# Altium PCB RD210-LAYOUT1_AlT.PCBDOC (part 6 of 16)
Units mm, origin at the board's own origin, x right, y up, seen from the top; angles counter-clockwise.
Board outline 330 x 300 mm, 6 copper layers (TOP, Mid-Layer 1, Mid-Layer 2, Mid-Layer 3, Mid-Layer 4, BOTTOM), stack 1.422 mm thick; 981 components, 463 nets, 2326 pads, 12534 vias.
Unrouted connection lines stored in the file: 6.
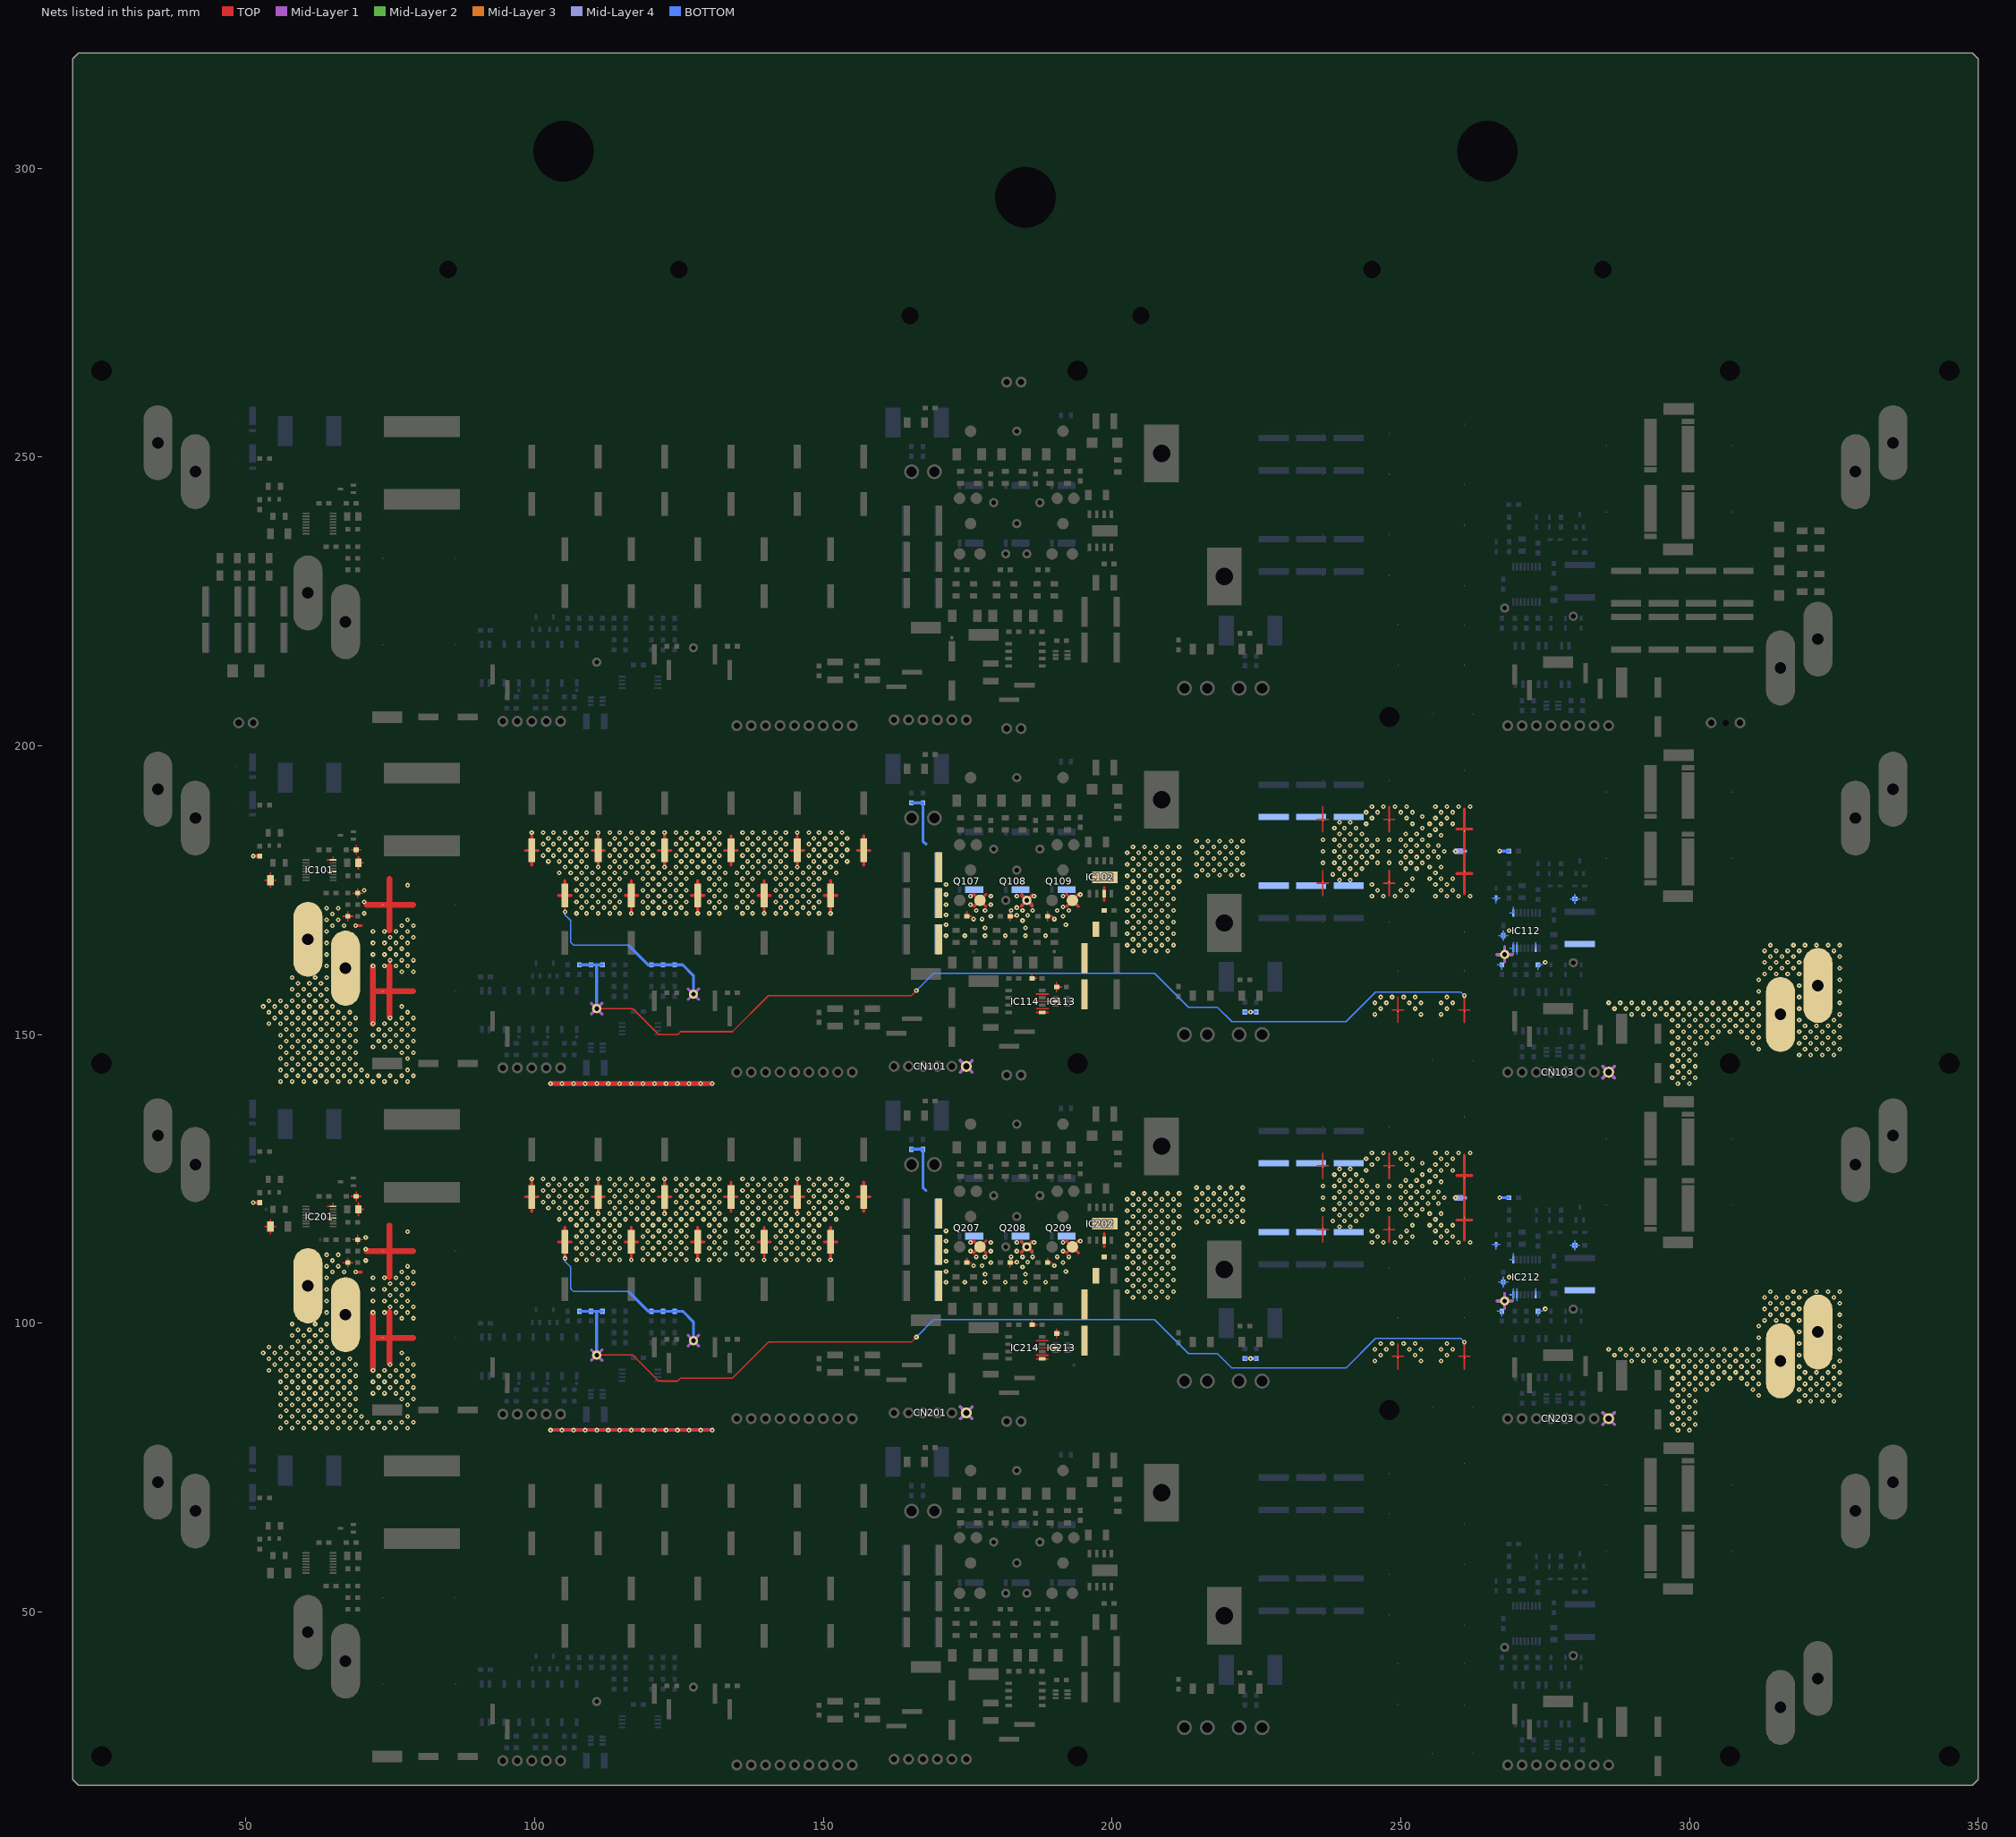
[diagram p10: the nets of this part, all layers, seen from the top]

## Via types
v1: diameter 0.8, hole 0.3, TOP to BOTTOM, 12534 vias

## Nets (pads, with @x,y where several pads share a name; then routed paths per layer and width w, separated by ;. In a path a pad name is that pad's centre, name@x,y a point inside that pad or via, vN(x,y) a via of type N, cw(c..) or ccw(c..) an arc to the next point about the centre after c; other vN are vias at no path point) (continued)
GND_P-2: C111.1 C113.1 C114.2 C115.1 C116.2 C117.2 C118.2 C119.2 C120.2 C121.2 C122.2 C123.2 C124.2 C125.2 C126.2 C127.2 C128.2 C129.1 C130.1 C131.1 C132.1 C133.1 C134.1 C135.1 C136.1 C137.2 C138.2 C139.1 C140.1 C142.2 C143.2 C149.2 C150.2 C151.2 C152.2 C153.2 C154.2 C155.2 C156.2 C157.2 C158.2 C159.1 C160.1 C161.1 C162.1 C163.1 C164.1 C179.1 C181.1 C183.2 C441.2 C445.2 CN101.6 CN103.1 CN116.1 CN117.1 CN120.1 CN134.1 D117.1 IC101.12 IC101.16 IC102.7 IC102.9 IC112.2 IC112.7 IC112.8 IC112.9 IC113.2 IC114.5 pad.@186.5,174 Q107.S Q108.S Q109.S R104.1 R122.2 R125.2 R128.2 R150.2 R151.1 R157.2 R158.1 R165.1 R188.1 R189.1 R193.1 TN22.1 TN22.2 TN24.1 TN24.2 TP117.1 TP119.1 | length 651.8
  TOP w0.25: 53.275,176.75 C113.1@54.225,176.75 ; 54.225,175.475 C113.1@54.225,176.75 ; 54.225,178.025 C113.1@54.225,176.75 ; 55.175,176.75 C113.1@54.225,176.75 ; 64.125,178.25 IC101.12@65.1,178.25 ; 64.125,180.25 IC101.16@65.1,180.25 65.1,180.76 ; 66.825,170.5 R104.1@67.65,170.5 ; 67.65,169.725 R104.1@67.65,170.5 ; 67.65,171.275 R104.1@67.65,170.5 ; 68.275,182 R165.1@69.1,182 ; 68.475,170.5 R104.1@67.65,170.5 ; 68.525,174.5 C115.1@69.35,174.5 ; 69.1,181.225 R165.1@69.1,182 ; 69.1,182.775 R165.1@69.1,182 ; 69.35,173.725 C115.1@69.35,174.5 ; 69.35,175.275 C115.1@69.35,174.5 ; 69.475,178.65 C114.2@69.475,179.75 ; 69.475,180.85 C114.2@69.475,179.75 ; 69.925,182 R165.1@69.1,182 ; 70.175,174.5 C115.1@69.35,174.5 ; 70.375,179.75 C114.2@69.475,179.75 ; v1(105.25,171.25) C128.2@105.25,174.1 ; CN117.1@110.75,154.5 117,154.5 121.5,150 124.75,150 125.25,150.5 134.25,150.5 140.5,156.75 165.25,156.75 v1(166.125,157.625) ; 174.85,171.275 R122.2@174.85,170.5 175.675,170.5 ; 182.35,169.725 R125.2@182.35,170.5 ; v1@182.35,171.275 R125.2@182.35,170.5 ; v1@183.175,170.5 R125.2@182.35,170.5 ; 186.15,160.525 C140.1@186.15,159.75 186.975,159.75 ; 186.875,154.48 189,154.48 ; 186.875,155.75 IC113.2@190.225,155.75 190.875,155.75 191.125,155.5 ; 186.875,157.02 189,157.02 ; 186.925,153.845 IC114.5@187.9,153.845 188.875,153.845 ; 188.85,169.725 R128.2@188.85,170.5 ; 188.85,171.275 R128.2@188.85,170.5 ; 189.675,170.5 R128.2@188.85,170.5 ; 190.4,157.475 C139.1@190.4,158.25 ; 190.4,159.025 C139.1@190.4,158.25 ; 191.225,158.25 C139.1@190.4,158.25 ; 235.523,176.225 236.5,176.225 ; 235.523,187.275 236.5,187.275 ; 236.5,174.023 236.5,176.225 ; 236.5,178.427 C153.2@236.5,176.5 236.5,176.225 ; 236.5,185.073 C151.2@236.5,187 236.5,187.275 ; 236.5,189.477 236.5,187.275 ; 237.477,176.225 236.5,176.225 ; 237.477,187.275 236.5,187.275 ; 247.023,176.225 248,176.225 ; 247.023,187.275 248,187.275 ; 248,174.023 248,176.225 ; 248,178.427 C154.2@248,176.5 248,176.225 ; 248,185.073 C152.2@248,187 248,187.275 ; 248,189.477 248,187.275 ; 248.523,154.275 249.5,154.275 ; 248.977,176.225 248,176.225 ; 248.977,187.275 248,187.275 ; 249.5,152.073 C155.2@249.5,154 249.5,154.275 ; 249.5,156.477 249.5,154.275 ; 250.477,154.275 249.5,154.275 ; 260.023,154.275 261,154.275 ; 261,152.073 C156.2@261,154 261,154.275 ; v1(261,156.75) 261,154.275 ; 261.977,154.275 261,154.275
  TOP w0.5: v1(51.242,180.917) C445.2@52.385,180.917 ; v1(69,168.875) 70,168.875 ; 98.4,181.9 C118.2@99.5,181.9 ; 99.5,179.35 C118.2@99.5,181.9 ; 99.5,184.45 C118.2@99.5,181.9 ; 100.6,181.9 C118.2@99.5,181.9 ; 104.15,174.1 C128.2@105.25,174.1 ; 105.25,176.65 C128.2@105.25,174.1 ; 106.35,174.1 C128.2@105.25,174.1 ; 109.9,181.9 C119.2@111,181.9 ; v1@111,179.35 C119.2@111,181.9 ; 111,184.45 C119.2@111,181.9 ; 112.1,181.9 C119.2@111,181.9 ; 115.65,174.1 C127.2@116.75,174.1 ; 116.75,171.55 C127.2@116.75,174.1 ; 116.75,176.65 C127.2@116.75,174.1 ; 117.85,174.1 C127.2@116.75,174.1 ; 121.4,181.9 C120.2@122.5,181.9 ; v1@122.5,179.35 C120.2@122.5,181.9 ; 122.5,184.45 C120.2@122.5,181.9 ; 123.6,181.9 C120.2@122.5,181.9 ; 127.15,174.1 C126.2@128.25,174.1 ; 128.25,171.55 C126.2@128.25,174.1 ; 128.25,176.65 C126.2@128.25,174.1 ; 129.35,174.1 C126.2@128.25,174.1 ; 132.9,181.9 C121.2@134,181.9 ; 134,179.35 C121.2@134,181.9 ; 134,184.45 C121.2@134,181.9 ; 135.1,181.9 C121.2@134,181.9 ; 138.65,174.1 C125.2@139.75,174.1 ; 139.75,171.55 C125.2@139.75,174.1 ; 139.75,176.65 C125.2@139.75,174.1 ; 140.85,174.1 C125.2@139.75,174.1 ; 144.4,181.9 C122.2@145.5,181.9 ; v1@145.5,179.35 C122.2@145.5,181.9 ; 145.5,184.45 C122.2@145.5,181.9 ; 146.6,181.9 C122.2@145.5,181.9 ; 150.15,174.1 C124.2@151.25,174.1 ; 151.25,171.55 C124.2@151.25,174.1 ; 151.25,176.65 C124.2@151.25,174.1 ; 152.35,174.1 C124.2@151.25,174.1 ; 155.9,181.9 C123.2@157,181.9 ; 157,179.35 C123.2@157,181.9 ; 157,184.45 C123.2@157,181.9 ; 158.1,181.9 C123.2@157,181.9 ; 176.064,172.189 TP117.1@177.125,173.25 ; 176.064,174.311 TP117.1@177.125,173.25 ; 178.186,172.189 TP117.1@177.125,173.25 ; 178.186,174.311 TP117.1@177.125,173.25 ; 184.331,172.331 CN134.1@185.25,173.25 ; 184.331,174.169 CN134.1@185.25,173.25 ; 186.125,172.375 CN134.1@185.25,173.25 ; v1@186.169,174.169 CN134.1@185.25,173.25 ; 192.064,172.189 TP119.1@193.125,173.25 ; 192.064,174.311 TP119.1@193.125,173.25 ; 194.186,172.189 TP119.1@193.125,173.25 ; v1@194.186,174.311 TP119.1@193.125,173.25 ; 198.635,173.25 IC102.7@198.635,174.4 198.635,175.55 ; 259.696,177.9 261,177.9 ; 259.696,185.6 261,185.6 ; 261,174.396 261,177.9 ; 261,181.404 C158.2@261,178.25 261,177.9 ; 261,182.096 C157.2@261,185.25 261,185.6 ; 261,189.104 261,185.6 ; 262.304,177.9 261,177.9 ; 262.304,185.6 261,185.6
  TOP w0.6: v1(102.75,141.5) v1(104.75,141.5) v1(106.75,141.5) v1(108.75,141.5) v1(110.75,141.5) v1(112.75,141.5) v1(114.75,141.5) v1(116.75,141.5) v1(118.75,141.5) v1(120.75,141.5) v1(122.75,141.5) v1(124.75,141.5) v1(126.75,141.5) v1(128.75,141.5) v1(130.75,141.5)
  TOP w1: 70.875,172.5 C116.2@73.7,172.5 74.85,172.5 ; v1(72,151.875) 72,157.5 ; v1(72,161.875) 72,157.5 ; v1@74.85,153.043 74.85,157.5 ; 74.85,161.957 74.85,157.5 ; 74.85,168.043 74.85,172.5 ; 74.85,176.957 74.85,172.5 ; 79,157.5 74.85,157.5 ; 79,172.5 74.85,172.5 ; 72,157.5 C117.2@73.7,157.5 74.85,157.5
  Mid-Layer 1 w0.5: 109.831,153.581 CN117.1@110.75,154.5 ; 109.831,155.419 CN117.1@110.75,154.5 ; 111.669,153.581 CN117.1@110.75,154.5 ; 111.669,155.419 CN117.1@110.75,154.5 ; 126.581,156.081 CN116.1@127.5,157 ; 126.581,157.919 CN116.1@127.5,157 ; 128.419,156.081 CN116.1@127.5,157 ; 128.419,157.919 CN116.1@127.5,157 ; 173.725,143.475 CN101.6@174.75,144.5 ; 173.725,145.525 CN101.6@174.75,144.5 ; 175.775,143.475 CN101.6@174.75,144.5 ; 175.775,145.525 CN101.6@174.75,144.5 ; 184.331,172.331 CN134.1@185.25,173.25 ; 184.331,174.169 CN134.1@185.25,173.25 ; 186.169,172.331 CN134.1@185.25,173.25 ; v1@186.169,174.169 CN134.1@185.25,173.25 ; 266.7,163.875 CN120.1@268,163.875 ; 268,162.575 CN120.1@268,163.875 ; 268,165.175 CN120.1@268,163.875 ; 269.3,163.875 CN120.1@268,163.875 ; 284.975,142.475 CN103.1@286,143.5 ; 284.975,144.525 CN103.1@286,143.5 ; 287.025,142.475 CN103.1@286,143.5 ; 287.025,144.525 CN103.1@286,143.5
  Mid-Layer 1 w0.8: v1(102.75,141.5) v1(104.75,141.5) v1(106.75,141.5) v1(108.75,141.5) v1(110.75,141.5) v1(112.75,141.5) v1(114.75,141.5) v1(116.75,141.5) v1(118.75,141.5) v1(120.75,141.5) v1(122.75,141.5) v1(124.75,141.5) v1(126.75,141.5) v1(128.75,141.5) v1(130.75,141.5)
  Mid-Layer 2 w0.5: 173.725,143.475 CN101.6@174.75,144.5 ; 173.725,145.525 CN101.6@174.75,144.5 ; 175.775,143.475 CN101.6@174.75,144.5 ; 175.775,145.525 CN101.6@174.75,144.5 ; 184.331,172.331 CN134.1@185.25,173.25 ; 184.331,174.169 CN134.1@185.25,173.25 ; 186.169,172.331 CN134.1@185.25,173.25 ; v1@186.169,174.169 CN134.1@185.25,173.25 ; 266.7,163.875 CN120.1@268,163.875 ; 268,162.575 CN120.1@268,163.875 ; 268,165.175 CN120.1@268,163.875 ; 269.3,163.875 CN120.1@268,163.875 ; 284.975,142.475 CN103.1@286,143.5 ; 284.975,144.525 CN103.1@286,143.5 ; 287.025,142.475 CN103.1@286,143.5 ; 287.025,144.525 CN103.1@286,143.5
  Mid-Layer 3 w0.5: 173.725,143.475 CN101.6@174.75,144.5 ; 173.725,145.525 CN101.6@174.75,144.5 ; 175.775,143.475 CN101.6@174.75,144.5 ; 175.775,145.525 CN101.6@174.75,144.5 ; 184.331,172.331 CN134.1@185.25,173.25 ; 184.331,174.169 CN134.1@185.25,173.25 ; 186.169,172.331 CN134.1@185.25,173.25 ; v1@186.169,174.169 CN134.1@185.25,173.25 ; 266.7,163.875 CN120.1@268,163.875 ; 268,162.575 CN120.1@268,163.875 ; 268,165.175 CN120.1@268,163.875 ; 269.3,163.875 CN120.1@268,163.875 ; 284.975,142.475 CN103.1@286,143.5 ; 284.975,144.525 CN103.1@286,143.5 ; 287.025,142.475 CN103.1@286,143.5 ; 287.025,144.525 CN103.1@286,143.5
  Mid-Layer 4 w1: v1(259.5,181.75) 261,181.75
  BOTTOM w0.25: v1(105.25,171.25) 105.25,170.75 106.25,169.75 106.25,166 106.75,165.5 116.25,165.5 116.375,165.375 ; v1(166.125,157.625) 169.125,160.625 207.375,160.625 213.25,154.75 218.25,154.75 220.75,152.25 240.5,152.25 245.625,157.375 260.375,157.375 v1(261,156.75) ; 265.875,173.65 D117.1@266.5,173.65 ; 266.5,172.825 D117.1@266.5,173.65 ; 266.725,162.1 R188.1@267.5,162.1 267.5,161.275 ; 266.975,167.15 C183.2@267.75,167.15 ; 267.125,173.65 D117.1@266.5,173.65 ; 267.75,166.325 C183.2@267.75,167.15 ; 267.75,167.975 C183.2@267.75,167.15 ; 268.525,167.15 C183.2@267.75,167.15 ; 268.9,164.95 IC112.8@269.475,164.95 ; 268.9,171.05 IC112.9@269.475,171.05 269.475,172.075 ; 269.475,163.925 IC112.8@269.475,164.95 ; 269.475,165.975 IC112.8@269.475,164.95 ; 270.125,163.925 IC112.7@270.125,164.95 270.125,165.975 ; IC112.2@273.375,164.95 273.375,165.975 ; 273.75,161.275 R189.1@273.75,162.1 274.525,162.1 ; 279.325,173.5 R193.1@280.15,173.5 ; 280.15,172.725 R193.1@280.15,173.5 ; 280.15,174.275 R193.1@280.15,173.5 ; 280.975,173.5 R193.1@280.15,173.5
  BOTTOM w0.5: C179.1@107.75,162.1 R157.2@109.75,162.1 110.5,162.1 ; CN117.1@110.75,154.5 110.75,161.85 ; R158.1@111.75,162.1 111,162.1 ; 116.375,165.375 119.65,162.1 R151.1@120.25,162.1 C111.1@122.25,162.1 R150.2@124.25,162.1 125.65,162.1 127.5,160.25 CN116.1@127.5,157 ; C143.2@165.25,190.15 C142.2@167.25,190.15 167.25,183.5 167.75,183 ; 184.331,172.331 CN134.1@185.25,173.25 ; 184.331,174.169 CN134.1@185.25,173.25 ; 186.169,172.331 CN134.1@185.25,173.25 ; v1@186.169,174.169 CN134.1@185.25,173.25 ; C149.2@223,153.9 v1(224,153.9) C150.2@225,153.9 ; 266.7,163.875 CN120.1@268,163.875 268,165.175 ; v1(267.142,181.775) C441.2@268.705,181.775 ; 110.5,162.1 110.75,161.85 ; 110.5,162.1 111,162.1 ; 110.75,161.85 111,162.1
  BOTTOM w0.6: v1(102.75,141.5) v1(104.75,141.5) v1(106.75,141.5) v1(108.75,141.5) v1(110.75,141.5) v1(112.75,141.5) v1(114.75,141.5) v1(116.75,141.5) v1(118.75,141.5) v1(120.75,141.5) v1(122.75,141.5) v1(124.75,141.5) v1(126.75,141.5) v1(128.75,141.5) v1(130.75,141.5)
  other v1: 298,141.5 300,141.5 56,141.875 58,141.875 60,141.875 62,141.875 64,141.875 66,141.875 68,141.875 70,141.875 72,141.875 74,141.875 76,141.875 78,141.875 297,142.5 299,142.5 301,142.5 57,142.875 59,142.875 61,142.875 63,142.875 65,142.875 67,142.875 69,142.875 71,142.875 73,142.875 75,142.875 77,142.875 79,142.875 298,143.5 300,143.5 56,143.875 58,143.875 60,143.875 62,143.875 64,143.875 66,143.875 68,143.875 70,143.875 78,143.875 297,144.5 299,144.5 301,144.5 57,144.875 59,144.875 61,144.875 63,144.875 65,144.875 67,144.875 69,144.875 298,145.5 300,145.5 56,145.875 58,145.875 60,145.875 62,145.875 64,145.875 66,145.875 68,145.875 78,145.875 297,146.5 299,146.5 301,146.5 319,146.5 321,146.5 323,146.5 325,146.5 57,146.875 59,146.875 61,146.875 63,146.875 65,146.875 67,146.875 69,146.875 77,146.875 79,146.875 298,147.5 300,147.5 312,147.5 320,147.5 322,147.5 324,147.5 326,147.5 56,147.875 58,147.875 60,147.875 62,147.875 64,147.875 66,147.875 68,147.875 72,147.875 74,147.875 76,147.875 78,147.875 297,148.5 299,148.5 301,148.5 303,148.5 311,148.5 319,148.5 321,148.5 323,148.5 325,148.5 57,148.875 59,148.875 61,148.875 63,148.875 65,148.875 67,148.875 69,148.875 73,148.875 75,148.875 77,148.875 79,148.875 298,149.5 300,149.5 302,149.5 304,149.5 310,149.5 312,149.5 320,149.5 322,149.5 324,149.5 326,149.5 56,149.875 58,149.875 60,149.875 62,149.875 64,149.875 66,149.875 68,149.875 72,149.875 74,149.875 76,149.875 78,149.875 297,150.5 299,150.5 301,150.5 303,150.5 305,150.5 307,150.5 309,150.5 311,150.5 319,150.5 321,150.5 323,150.5 325,150.5 57,150.875 59,150.875 61,150.875 63,150.875 65,150.875 67,150.875 69,150.875 73,150.875 75,150.875 77,150.875 79,150.875 298,151.5 300,151.5 302,151.5 304,151.5 306,151.5 308,151.5 310,151.5 312,151.5 320,151.5 322,151.5 324,151.5 326,151.5 54,151.875 56,151.875 58,151.875 60,151.875 62,151.875 64,151.875 66,151.875 68,151.875 74,151.875 76,151.875 78,151.875 297,152.5 299,152.5 301,152.5 303,152.5 305,152.5 307,152.5 309,152.5 311,152.5 319,152.5 325,152.5 55,152.875 57,152.875 59,152.875 61,152.875 63,152.875 65,152.875 67,152.875 69,152.875 75,152.875 77,152.875 79,152.875 245.5,153.5 253.5,153.5 257,153.5 290,153.5 292,153.5 294,153.5 296,153.5 298,153.5 300,153.5 302,153.5 304,153.5 306,153.5 308,153.5 310,153.5 312,153.5 326,153.5 54,153.875 56,153.875 58,153.875 60,153.875 62,153.875 64,153.875 66,153.875 68,153.875 78,153.875 246.5,154.5 252.5,154.5 258,154.5 287,154.5 289,154.5 291,154.5 293,154.5 295,154.5 297,154.5 299,154.5 301,154.5 303,154.5 305,154.5 307,154.5 309,154.5 311,154.5 319,154.5 53,154.875 55,154.875 57,154.875 59,154.875 61,154.875 63,154.875 65,154.875 77,154.875 245.5,155.5 247.5,155.5 251.5,155.5 253.5,155.5 257,155.5 259,155.5 286,155.5 288,155.5 290,155.5 292,155.5 294,155.5 296,155.5 298,155.5 300,155.5 302,155.5 304,155.5 306,155.5 308,155.5 310,155.5 312,155.5 326,155.5 54,155.875 56,155.875 58,155.875 60,155.875 62,155.875 64,155.875 246.5,156.5 248.5,156.5 250.5,156.5 252.5,156.5 258,156.5 319,156.5 59,156.875 61,156.875 63,156.875 312,157.5 326,157.5 58,157.875 60,157.875 62,157.875 64,157.875 319,158.5 59,158.875 61,158.875 63,158.875 312,159.5 326,159.5 58,159.875 62,159.875 64,159.875 313,160.5 315,160.5 317,160.5 319,160.5 77,160.875 79,160.875 314,161.5 316,161.5 318,161.5 326,161.5 64,161.875 74,161.875 76,161.875 78,161.875 275,162.5 313,162.5 315,162.5 317,162.5 319,162.5 75,162.875 77,162.875 79,162.875 314,163.5 316,163.5 318,163.5 326,163.5 64,163.875 72,163.875 74,163.875 76,163.875 78,163.875 203.625,164.5 205.625,164.5 207.625,164.5 209.625,164.5 313,164.5 315,164.5 317,164.5 319,164.5 325,164.5 75,164.875 77,164.875 202.625,165.5 204.625,165.5 206.625,165.5 208.625,165.5 210.625,165.5 314,165.5 318,165.5 320,165.5 322,165.5 324,165.5 326,165.5 64,165.875 72,165.875 74,165.875 76,165.875 78,165.875 203.625,166.5 205.625,166.5 207.625,166.5 209.625,166.5 75,166.875 77,166.875 79,166.875 171.25,167.125 174.5,167.125 178,167.125 181.5,167.125 185,167.125 188.5,167.125 202.625,167.5 204.625,167.5 206.625,167.5 208.625,167.5 210.625,167.5 64,167.875 72,167.875 74,167.875 76,167.875 78,167.875 268.75,168 178,168.5 185,168.5 203.625,168.5 205.625,168.5 207.625,168.5 209.625,168.5 65,168.875 67,168.875 77,168.875 79,168.875 171.25,169 192,169 202.625,169.5 204.625,169.5 206.625,169.5 208.625,169.5 210.625,169.5 184.5,169.75 64,169.875 66,169.875 78,169.875 176,170 177.5,170 190,170 179,170.5 191.5,170.5 203.625,170.5 205.625,170.5 207.625,170.5 209.625,170.5 183.5,170.625 185.375,170.625 171.25,170.75 65,170.875 70.5,171 107.25,171 109,171 111,171 113,171 114.75,171 116.75,171 118.75,171 120.5,171 122.5,171 124.5,171 126.25,171 128.25,171 130.25,171 132,171 136,171 137.75,171 139.75,171 141.75,171 143.5,171 145.5,171 147.5,171 149.25,171 151.25,171 176.5,171.5 178,171.5 182.5,171.5 184.5,171.5 186.25,171.5 190.5,171.5 192.5,171.5 202.625,171.5 204.625,171.5 206.625,171.5 208.625,171.5 210.625,171.5 64,171.875 66,171.875 108.125,172 110,172 112,172 113.875,172 119.625,172 121.5,172 123.5,172 125.375,172 131.125,172 133,172 135,172 136.875,172 142.625,172 144.5,172 146.5,172 148.375,172 183.5,172 191.5,172.125 171.25,172.5 175.5,172.5 179,172.5 203.625,172.5 205.625,172.5 207.625,172.5 209.625,172.5 70.5,173 107.25,173 109,173 111,173 113,173 114.75,173 118.75,173 120.5,173 122.5,173 124.5,173 126.25,173 130.25,173 132,173 136,173 137.75,173 141.75,173 143.5,173 145.5,173 147.5,173 149.25,173 202.625,173.5 204.625,173.5 206.625,173.5 208.625,173.5 210.625,173.5 108.125,174 110,174 112,174 113.875,174 119.625,174 121.5,174 123.5,174 125.375,174 131.125,174 133,174 135,174 136.875,174 142.625,174 144.5,174 146.5,174 148.375,174 175.5,174 179,174 183.5,174 186.5,174 191.5,174 245,174 247,174 249,174 251,174 256,174 258,174 260,174 262,174 171.25,174.25 194.5,174.25 203.625,174.5 205.625,174.5 207.625,174.5 209.625,174.5 70.5,175 107.25,175 109,175 111,175 113,175 114.75,175 118.75,175 120.5,175 122.5,175 124.5,175 126.25,175 130.25,175 132,175 136,175 137.75,175 141.75,175 143.5,175 145.5,175 147.5,175 149.25,175 246,175 250,175 252,175 257,175 259,175 202.625,175.5 204.625,175.5 206.625,175.5 208.625,175.5 210.625,175.5 78,175.875 108.125,176 110,176 112,176 113.875,176 119.625,176 121.5,176 123.5,176 125.375,176 131.125,176 133,176 135,176 136.875,176 142.625,176 144.5,176 146.5,176 148.375,176 171.25,176 245,176 251,176 256,176 258,176 203.625,176.5 205.625,176.5 207.625,176.5 209.625,176.5 211.625,176.5 239.375,176.75 241.25,176.75 107.25,177 109,177 111,177 113,177 114.75,177 118.75,177 120.5,177 122.5,177 124.5,177 126.25,177 130.25,177 132,177 136,177 137.75,177 141.75,177 143.5,177 145.5,177 147.5,177 149.25,177 252,177 255,177 257,177 259,177 202.625,177.5 204.625,177.5 206.625,177.5 208.625,177.5 210.625,177.5 214.625,177.5 216.625,177.625 218.625,177.625 220.625,177.625 222.625,177.625 238.25,177.75 240.25,177.75 242.25,177.75 104.25,178 106.25,178 108.125,178 110,178 112,178 113.875,178 115.75,178 117.75,178 119.625,178 121.5,178 123.5,178 125.375,178 127.25,178 129.25,178 131.125,178 133,178 135,178 136.875,178 138.75,178 140.75,178 142.625,178 144.5,178 146.5,178 148.375,178 150.25,178 152.25,178 256,178 203.625,178.5 205.625,178.5 207.625,178.5 209.625,178.5 211.625,178.5 215.625,178.5 217.625,178.5 219.625,178.5 221.625,178.5 239.375,178.75 241.25,178.75 243.25,178.75 250.875,178.75 252.75,178.75 105.25,179 107.25,179 109,179 111,179 113,179 114.75,179 116.75,179 118.75,179 120.5,179 122.5,179 124.5,179 126.25,179 128.25,179 130.25,179 132,179 136,179 137.75,179 139.75,179 141.75,179 143.5,179 145.5,179 147.5,179 149.25,179 151.25,179 255,179 257,179 202.625,179.5 204.625,179.5 206.625,179.5 208.625,179.5 210.625,179.5 214.625,179.5 216.625,179.5 218.625,179.5 220.625,179.5 222.625,179.5 236.5,179.75 238.5,179.75 240.25,179.75 242.25,179.75 244.125,179.75 246,179.75 248,179.75 250,179.75 251.75,179.75 253.75,179.75 102.375,180 104.25,180 106.25,180 108.125,180 113.875,180 115.75,180 117.75,180 119.625,180 125.375,180 127.25,180 129.25,180 131.125,180 136.875,180 138.75,180 140.75,180 142.625,180 148.375,180 150.25,180 152.25,180 154.125,180 203.625,180.5 205.625,180.5 207.625,180.5 209.625,180.5 211.625,180.5 215.625,180.5 217.625,180.5 219.625,180.5 221.625,180.5 239.375,180.75 241.25,180.75 243.25,180.75 245,180.75 250.875,180.75 252.75,180.75 254.75,180.75 256.5,180.75 101.5,181 103.25,181 105.25,181 107.25,181 109,181 113,181 114.75,181 116.75,181 118.75,181 120.5,181 124.5,181 126.25,181 128.25,181 130.25,181 132,181 136,181 137.75,181 139.75,181 141.75,181 143.5,181 147.5,181 149.25,181 151.25,181 153.25,181 202.625,181.5 204.625,181.5 206.625,181.5 208.625,181.5 210.625,181.5 214.625,181.5 216.625,181.5 218.625,181.5 220.625,181.5 222.625,181.5 236.5,181.75 238.5,181.75 240.25,181.75 242.25,181.75 244.125,181.75 246,181.75 248,181.75 250,181.75 251.75,181.75 253.75,181.75 255.75,181.75 257.5,181.75 102.375,182 104.25,182 106.25,182 108.125,182 113.875,182 115.75,182 117.75,182 119.625,182 125.375,182 127.25,182 129.25,182 131.125,182 136.875,182 138.75,182 140.75,182 142.625,182 148.375,182 150.25,182 152.25,182 154.125,182 203.625,182.5 205.625,182.5 207.625,182.5 209.625,182.5 211.625,182.5 215.625,182.5 217.625,182.5 219.625,182.5 221.625,182.5 239.375,182.75 241.25,182.75 243.25,182.75 245,182.75 250.875,182.75 252.75,182.75 254.75,182.75 256.5,182.75 101.5,183 103.25,183 105.25,183 107.25,183 109,183 113,183 114.75,183 116.75,183 118.75,183 120.5,183 124.5,183 126.25,183 128.25,183 130.25,183 132,183 136,183 137.75,183 139.75,183 141.75,183 143.5,183 147.5,183 149.25,183 151.25,183 153.25,183 214.625,183.5 216.625,183.5 218.625,183.5 220.625,183.5 222.625,183.5 236.5,183.75 238.5,183.75 240.25,183.75 242.25,183.75 244.125,183.75 246,183.75 248,183.75 250,183.75 251.75,183.75 253.75,183.75 102.375,184 104.25,184 106.25,184 108.125,184 113.875,184 115.75,184 117.75,184 119.625,184 125.375,184 127.25,184 129.25,184 131.125,184 136.875,184 138.75,184 140.75,184 142.625,184 148.375,184 150.25,184 152.25,184 154.125,184 255,184.5 257,184.5 239.375,184.75 241.25,184.75 243.25,184.75 250.875,184.75 252.75,184.75 99.5,185 101.5,185 103.25,185 105.25,185 107.25,185 109,185 111,185 113,185 114.75,185 116.75,185 118.75,185 120.5,185 122.5,185 124.5,185 126.25,185 128.25,185 130.25,185 132,185 136,185 137.75,185 139.75,185 141.75,185 143.5,185 145.5,185 147.5,185 149.25,185 151.25,185 153.25,185 256,185.5 238.5,185.75 240.25,185.75 242.25,185.75 253.75,185.75 244,186.5 252,186.5 255,186.5 257,186.5 259,186.5 239.375,186.75 241.25,186.75 245,187.5 251,187.5 256,187.5 258,187.5 253.75,187.75 244,188.5 246,188.5 250,188.5 252,188.5 257,188.5 259,188.5 245,189.5 247,189.5 249,189.5 251,189.5 256,189.5 258,189.5 260,189.5 262,189.5
GND_P-3: C211.1 C213.1 C214.2 C215.1 C216.2 C217.2 C218.2 C219.2 C220.2 C221.2 C222.2 C223.2 C224.2 C225.2 C226.2 C227.2 C228.2 C229.1 C230.1 C231.1 C232.1 C233.1 C234.1 C235.1 C236.1 C237.2 C238.2 C239.1 C240.1 C242.2 C243.2 C249.2 C250.2 C251.2 C252.2 C253.2 C254.2 C255.2 C256.2 C257.2 C258.2 C259.1 C260.1 C261.1 C262.1 C263.1 C264.1 C279.1 C281.1 C283.2 C442.2 C446.2 CN201.6 CN203.1 CN216.1 CN217.1 CN220.1 CN234.1 D217.1 IC201.12 IC201.16 IC202.7 IC202.9 IC212.2 IC212.7 IC212.8 IC212.9 IC213.2 IC214.5 Q207.S Q208.S Q209.S R204.1 R222.2 R225.2 R228.2 R250.2 R251.1 R257.2 R258.1 R265.1 R288.1 R289.1 R293.1 TN32.1 TN32.2 TN34.1 TN34.2 TP217.1 TP219.1 | length 650.8
  TOP w0.25: 53.275,116.75 C213.1@54.225,116.75 ; 54.225,115.475 C213.1@54.225,116.75 ; 54.225,118.025 C213.1@54.225,116.75 ; 55.175,116.75 C213.1@54.225,116.75 ; 64.125,118.25 IC201.12@65.1,118.25 ; 64.125,120.25 IC201.16@65.1,120.25 65.1,120.76 ; 66.825,110.5 R204.1@67.65,110.5 ; 67.65,109.725 R204.1@67.65,110.5 ; 67.65,111.275 R204.1@67.65,110.5 ; 68.275,122 R265.1@69.1,122 ; 68.475,110.5 R204.1@67.65,110.5 ; 68.525,114.5 C215.1@69.35,114.5 ; 69.1,121.225 R265.1@69.1,122 ; 69.1,122.775 R265.1@69.1,122 ; 69.35,113.725 C215.1@69.35,114.5 ; 69.35,115.275 C215.1@69.35,114.5 ; 69.475,118.65 C214.2@69.475,119.75 ; 69.475,120.85 C214.2@69.475,119.75 ; 69.925,122 R265.1@69.1,122 ; 70.175,114.5 C215.1@69.35,114.5 ; 70.375,119.75 C214.2@69.475,119.75 ; CN217.1@110.75,94.5 117,94.5 121.5,90 124.75,90 125.25,90.5 134.25,90.5 140.5,96.75 165.25,96.75 v1(166.125,97.625) ; 174.85,111.275 R222.2@174.85,110.5 175.675,110.5 ; 182.35,109.725 R225.2@182.35,110.5 ; v1@182.35,111.275 R225.2@182.35,110.5 ; v1@183.175,110.5 R225.2@182.35,110.5 ; 186.15,100.525 C240.1@186.15,99.75 186.975,99.75 ; 186.875,95.75 IC213.2@190.225,95.75 190.89,95.75 191.17,95.47 ; 186.875,97.02 188.875,97.02 ; 186.9,94.48 188.875,94.48 ; 186.925,93.845 IC214.5@187.9,93.845 188.875,93.845 ; 188.85,111.275 R228.2@188.85,110.5 189.675,110.5 ; 190.4,97.475 C239.1@190.4,98.25 ; 190.4,99.025 C239.1@190.4,98.25 ; 191.225,98.25 C239.1@190.4,98.25 ; 235.523,116.225 236.5,116.225 ; 235.523,127.275 236.5,127.275 ; 236.5,114.023 236.5,116.225 ; 236.5,118.427 C253.2@236.5,116.5 236.5,116.225 ; 236.5,125.073 C251.2@236.5,127 236.5,127.275 ; 236.5,129.477 236.5,127.275 ; 237.477,116.225 236.5,116.225 ; 237.477,127.275 236.5,127.275 ; 247.023,116.225 248,116.225 ; 247.023,127.275 248,127.275 ; 248,114.023 248,116.225 ; 248,118.427 C254.2@248,116.5 248,116.225 ; 248,125.073 C252.2@248,127 248,127.275 ; 248,129.477 248,127.275 ; 248.523,94.275 249.5,94.275 ; 248.977,116.225 248,116.225 ; 248.977,127.275 248,127.275 ; 249.5,92.073 C256.2@249.5,94 249.5,94.275 ; 249.5,96.477 249.5,94.275 ; 250.477,94.275 249.5,94.275 ; 260.023,94.275 261,94.275 ; 261,92.073 C255.2@261,94 261,94.275 ; v1(261,96.75) 261,94.275 ; 261.977,94.275 261,94.275
  TOP w0.5: v1(51.242,120.91) C446.2@52.385,120.91 ; v1(69,108.875) 70,108.875 ; 98.4,121.9 C218.2@99.5,121.9 ; 99.5,119.35 C218.2@99.5,121.9 ; 99.5,124.45 C218.2@99.5,121.9 ; 100.6,121.9 C218.2@99.5,121.9 ; 104.15,114.1 C228.2@105.25,114.1 ; v1(105.25,111.25) C228.2@105.25,114.1 ; 105.25,116.65 C228.2@105.25,114.1 ; 106.35,114.1 C228.2@105.25,114.1 ; 109.9,121.9 C219.2@111,121.9 ; v1@111,119.35 C219.2@111,121.9 ; 111,124.45 C219.2@111,121.9 ; 112.1,121.9 C219.2@111,121.9 ; 115.65,114.1 C227.2@116.75,114.1 ; 116.75,111.55 C227.2@116.75,114.1 ; 116.75,116.65 C227.2@116.75,114.1 ; 117.85,114.1 C227.2@116.75,114.1 ; 121.4,121.9 C220.2@122.5,121.9 ; v1@122.5,119.35 C220.2@122.5,121.9 ; 122.5,124.45 C220.2@122.5,121.9 ; 123.6,121.9 C220.2@122.5,121.9 ; 127.15,114.1 C226.2@128.25,114.1 ; 128.25,111.55 C226.2@128.25,114.1 ; 128.25,116.65 C226.2@128.25,114.1 ; 129.35,114.1 C226.2@128.25,114.1 ; 132.9,121.9 C221.2@134,121.9 ; 134,119.35 C221.2@134,121.9 ; 134,124.45 C221.2@134,121.9 ; 135.1,121.9 C221.2@134,121.9 ; 138.65,114.1 C225.2@139.75,114.1 ; 139.75,111.55 C225.2@139.75,114.1 ; 139.75,116.65 C225.2@139.75,114.1 ; 140.85,114.1 C225.2@139.75,114.1 ; 144.4,121.9 C222.2@145.5,121.9 ; v1@145.5,119.35 C222.2@145.5,121.9 ; 145.5,124.45 C222.2@145.5,121.9 ; 146.6,121.9 C222.2@145.5,121.9 ; 150.15,114.1 C224.2@151.25,114.1 ; 151.25,111.55 C224.2@151.25,114.1 ; 151.25,116.65 C224.2@151.25,114.1 ; 152.35,114.1 C224.2@151.25,114.1 ; 155.9,121.9 C223.2@157,121.9 ; 157,119.35 C223.2@157,121.9 ; 157,124.45 C223.2@157,121.9 ; 158.1,121.9 C223.2@157,121.9 ; 176.064,112.189 TP217.1@177.125,113.25 ; 176.064,114.311 TP217.1@177.125,113.25 ; 178.186,112.189 TP217.1@177.125,113.25 ; 178.186,114.311 TP217.1@177.125,113.25 ; 184.331,112.331 CN234.1@185.25,113.25 ; 184.331,114.169 CN234.1@185.25,113.25 ; 186.125,112.375 CN234.1@185.25,113.25 ; v1@186.169,114.169 CN234.1@185.25,113.25 ; 192.064,112.189 TP219.1@193.125,113.25 ; 192.064,114.311 TP219.1@193.125,113.25 ; 194.186,112.189 TP219.1@193.125,113.25 ; v1@194.186,114.311 TP219.1@193.125,113.25 ; 198.635,113.25 IC202.7@198.635,114.4 198.635,115.55 ; 259.696,117.9 261,117.9 ; 259.696,125.6 261,125.6 ; 261,114.396 261,117.9 ; 261,121.404 C258.2@261,118.25 261,117.9 ; 261,122.096 C257.2@261,125.25 261,125.6 ; 261,129.104 261,125.6 ; 262.304,117.9 261,117.9 ; 262.304,125.6 261,125.6
  TOP w0.6: v1(102.75,81.5) v1(104.75,81.5) v1(106.75,81.5) v1(108.75,81.5) v1(110.75,81.5) v1(112.75,81.5) v1(114.75,81.5) v1(116.75,81.5) v1(118.75,81.5) v1(120.75,81.5) v1(122.75,81.5) v1(124.75,81.5) v1(126.75,81.5) v1(128.75,81.5) v1(130.75,81.5)
  TOP w1: v1@70.875,112.5 C216.2@73.7,112.5 74.85,112.5 ; v1(72,91.875) 72,97.5 ; v1(72,101.875) 72,97.5 ; v1@74.85,93.043 74.85,97.5 ; 74.85,101.957 74.85,97.5 ; 74.85,108.043 74.85,112.5 ; 74.85,116.957 74.85,112.5 ; 79,97.5 74.85,97.5 ; 79,112.5 74.85,112.5 ; 72,97.5 C217.2@73.7,97.5 74.85,97.5
  Mid-Layer 1 w0.5: 109.831,93.581 CN217.1@110.75,94.5 ; 109.831,95.419 CN217.1@110.75,94.5 ; 111.669,93.581 CN217.1@110.75,94.5 ; 111.669,95.419 CN217.1@110.75,94.5 ; 126.581,96.081 CN216.1@127.5,97 ; 126.581,97.919 CN216.1@127.5,97 ; 128.419,96.081 CN216.1@127.5,97 ; 128.419,97.919 CN216.1@127.5,97 ; 173.725,83.475 CN201.6@174.75,84.5 ; 173.725,85.525 CN201.6@174.75,84.5 ; 175.775,83.475 CN201.6@174.75,84.5 ; 175.775,85.525 CN201.6@174.75,84.5 ; 184.331,112.331 CN234.1@185.25,113.25 ; 184.331,114.169 CN234.1@185.25,113.25 ; 186.169,112.331 CN234.1@185.25,113.25 ; v1@186.169,114.169 CN234.1@185.25,113.25 ; 266.7,103.875 CN220.1@268,103.875 ; 268,102.575 CN220.1@268,103.875 ; 268,105.175 CN220.1@268,103.875 ; 269.3,103.875 CN220.1@268,103.875 ; 284.975,82.475 CN203.1@286,83.5 ; 284.975,84.525 CN203.1@286,83.5 ; 287.025,82.475 CN203.1@286,83.5 ; 287.025,84.525 CN203.1@286,83.5
  Mid-Layer 1 w0.6: v1(102.75,81.5) v1(104.75,81.5) v1(106.75,81.5) v1(108.75,81.5) v1(110.75,81.5) v1(112.75,81.5) v1(114.75,81.5) v1(116.75,81.5) v1(118.75,81.5) v1(120.75,81.5) v1(122.75,81.5) v1(124.75,81.5) v1(126.75,81.5) v1(128.75,81.5) v1(130.75,81.5)
  Mid-Layer 2 w0.5: 173.725,83.475 CN201.6@174.75,84.5 ; 173.725,85.525 CN201.6@174.75,84.5 ; 175.775,83.475 CN201.6@174.75,84.5 ; 175.775,85.525 CN201.6@174.75,84.5 ; 184.331,112.331 CN234.1@185.25,113.25 ; 184.331,114.169 CN234.1@185.25,113.25 ; 186.169,112.331 CN234.1@185.25,113.25 ; v1@186.169,114.169 CN234.1@185.25,113.25 ; 266.7,103.875 CN220.1@268,103.875 ; 268,102.575 CN220.1@268,103.875 ; 268,105.175 CN220.1@268,103.875 ; 269.3,103.875 CN220.1@268,103.875 ; 284.975,82.475 CN203.1@286,83.5 ; 284.975,84.525 CN203.1@286,83.5 ; 287.025,82.475 CN203.1@286,83.5 ; 287.025,84.525 CN203.1@286,83.5
  Mid-Layer 3 w0.5: 173.725,83.475 CN201.6@174.75,84.5 ; 173.725,85.525 CN201.6@174.75,84.5 ; 175.775,83.475 CN201.6@174.75,84.5 ; 175.775,85.525 CN201.6@174.75,84.5 ; 184.331,112.331 CN234.1@185.25,113.25 ; 184.331,114.169 CN234.1@185.25,113.25 ; 186.169,112.331 CN234.1@185.25,113.25 ; v1@186.169,114.169 CN234.1@185.25,113.25 ; 266.7,103.875 CN220.1@268,103.875 ; 268,102.575 CN220.1@268,103.875 ; 268,105.175 CN220.1@268,103.875 ; 269.3,103.875 CN220.1@268,103.875 ; 284.975,82.475 CN203.1@286,83.5 ; 284.975,84.525 CN203.1@286,83.5 ; 287.025,82.475 CN203.1@286,83.5 ; 287.025,84.525 CN203.1@286,83.5
  Mid-Layer 4 w1: v1(259.5,121.75) 261,121.75
  BOTTOM w0.25: v1(105.25,111.25) 105.25,110.75 106.25,109.75 106.25,106 106.75,105.5 116.25,105.5 116.375,105.375 ; v1(166.125,97.625) 169.125,100.625 207.375,100.625 213.25,94.75 218.25,94.75 220.75,92.25 240.5,92.25 245.625,97.375 260.375,97.375 v1(261,96.75) ; 265.875,113.65 D217.1@266.5,113.65 ; 266.5,112.825 D217.1@266.5,113.65 ; 266.725,102.1 R288.1@267.5,102.1 267.5,101.275 ; 266.975,107.15 C283.2@267.75,107.15 ; 267.125,113.65 D217.1@266.5,113.65 ; 267.75,106.325 C283.2@267.75,107.15 ; 267.75,107.975 C283.2@267.75,107.15 ; 268.525,107.15 C283.2@267.75,107.15 ; 268.9,104.95 IC212.8@269.475,104.95 ; 268.9,111.05 IC212.9@269.475,111.05 269.475,112.075 ; 269.475,103.925 IC212.8@269.475,104.95 ; 269.475,105.975 IC212.8@269.475,104.95 ; 270.125,103.925 IC212.7@270.125,104.95 270.125,105.975 ; IC212.2@273.375,104.95 273.375,105.975 ; 273.75,101.275 R289.1@273.75,102.1 274.525,102.1 ; 279.325,113.5 R293.1@280.15,113.5 ; 280.15,112.725 R293.1@280.15,113.5 ; 280.15,114.275 R293.1@280.15,113.5 ; 280.975,113.5 R293.1@280.15,113.5
  BOTTOM w0.5: C279.1@107.75,102.1 R257.2@109.75,102.1 110.5,102.1 ; CN217.1@110.75,94.5 110.75,101.85 ; R258.1@111.75,102.1 111,102.1 ; 116.375,105.375 119.65,102.1 R251.1@120.25,102.1 C211.1@122.25,102.1 R250.2@124.25,102.1 125.65,102.1 127.5,100.25 CN216.1@127.5,97 ; C243.2@165.25,130.15 C242.2@167.25,130.15 167.25,123.5 167.75,123 ; 184.331,112.331 CN234.1@185.25,113.25 ; 184.331,114.169 CN234.1@185.25,113.25 ; 186.169,112.331 CN234.1@185.25,113.25 ; v1@186.169,114.169 CN234.1@185.25,113.25 ; C249.2@223,93.9 v1(224,93.9) C250.2@225,93.9 ; 266.7,103.875 CN220.1@268,103.875 268,105.175 ; v1(267.142,121.775) C442.2@268.705,121.775 ; 110.5,102.1 110.75,101.85 ; 110.5,102.1 111,102.1 ; 110.75,101.85 111,102.1
  BOTTOM w0.6: v1(102.75,81.5) v1(104.75,81.5) v1(106.75,81.5) v1(108.75,81.5) v1(110.75,81.5) v1(112.75,81.5) v1(114.75,81.5) v1(116.75,81.5) v1(118.75,81.5) v1(120.75,81.5) v1(122.75,81.5) v1(124.75,81.5) v1(126.75,81.5) v1(128.75,81.5) v1(130.75,81.5)
  other v1: 298,81.5 300,81.5 56,81.875 58,81.875 60,81.875 62,81.875 64,81.875 66,81.875 68,81.875 70,81.875 72,81.875 74,81.875 76,81.875 78,81.875 297,82.5 299,82.5 301,82.5 57,82.875 59,82.875 61,82.875 63,82.875 65,82.875 67,82.875 69,82.875 71,82.875 73,82.875 75,82.875 77,82.875 79,82.875 298,83.5 300,83.5 56,83.875 58,83.875 60,83.875 62,83.875 64,83.875 66,83.875 68,83.875 70,83.875 78,83.875 297,84.5 299,84.5 301,84.5 57,84.875 59,84.875 61,84.875 63,84.875 65,84.875 67,84.875 69,84.875 298,85.5 300,85.5 56,85.875 58,85.875 60,85.875 62,85.875 64,85.875 66,85.875 68,85.875 78,85.875 297,86.5 299,86.5 301,86.5 319,86.5 321,86.5 323,86.5 325,86.5 57,86.875 59,86.875 61,86.875 63,86.875 65,86.875 67,86.875 69,86.875 77,86.875 79,86.875 298,87.5 300,87.5 312,87.5 320,87.5 322,87.5 324,87.5 326,87.5 56,87.875 58,87.875 60,87.875 62,87.875 64,87.875 66,87.875 68,87.875 72,87.875 74,87.875 76,87.875 78,87.875 297,88.5 299,88.5 301,88.5 303,88.5 311,88.5 319,88.5 321,88.5 323,88.5 325,88.5 57,88.875 59,88.875 61,88.875 63,88.875 65,88.875 67,88.875 69,88.875 73,88.875 75,88.875 77,88.875 79,88.875 298,89.5 300,89.5 302,89.5 304,89.5 310,89.5 312,89.5 320,89.5 322,89.5 324,89.5 326,89.5 56,89.875 58,89.875 60,89.875 62,89.875 64,89.875 66,89.875 68,89.875 72,89.875 74,89.875 76,89.875 78,89.875 297,90.5 299,90.5 301,90.5 303,90.5 305,90.5 307,90.5 309,90.5 311,90.5 319,90.5 321,90.5 323,90.5 325,90.5 57,90.875 59,90.875 61,90.875 63,90.875 65,90.875 67,90.875 69,90.875 73,90.875 75,90.875 77,90.875 79,90.875 298,91.5 300,91.5 302,91.5 304,91.5 306,91.5 308,91.5 310,91.5 312,91.5 320,91.5 322,91.5 324,91.5 326,91.5 54,91.875 56,91.875 58,91.875 60,91.875 62,91.875 64,91.875 66,91.875 68,91.875 74,91.875 76,91.875 78,91.875 297,92.5 299,92.5 301,92.5 303,92.5 305,92.5 307,92.5 309,92.5 311,92.5 319,92.5 325,92.5 55,92.875 57,92.875 59,92.875 61,92.875 63,92.875 65,92.875 67,92.875 69,92.875 75,92.875 77,92.875 79,92.875 245.5,93.5 253.5,93.5 257,93.5 290,93.5 292,93.5 294,93.5 296,93.5 298,93.5 300,93.5 302,93.5 304,93.5 306,93.5 308,93.5 310,93.5 312,93.5 326,93.5 54,93.875 56,93.875 58,93.875 60,93.875 62,93.875 64,93.875 66,93.875 68,93.875 78,93.875 246.5,94.5 252.5,94.5 258,94.5 287,94.5 289,94.5 291,94.5 293,94.5 295,94.5 297,94.5 299,94.5 301,94.5 303,94.5 305,94.5 307,94.5 309,94.5 311,94.5 319,94.5 53,94.875 55,94.875 57,94.875 59,94.875 61,94.875 63,94.875 65,94.875 77,94.875 245.5,95.5 247.5,95.5 251.5,95.5 253.5,95.5 257,95.5 259,95.5 286,95.5 288,95.5 290,95.5 292,95.5 294,95.5 296,95.5 298,95.5 300,95.5 302,95.5 304,95.5 306,95.5 308,95.5 310,95.5 312,95.5 326,95.5 54,95.875 56,95.875 58,95.875 60,95.875 62,95.875 64,95.875 246.5,96.5 248.5,96.5 250.5,96.5 252.5,96.5 258,96.5 319,96.5 59,96.875 61,96.875 63,96.875 312,97.5 326,97.5 58,97.875 60,97.875 62,97.875 64,97.875 319,98.5 59,98.875 61,98.875 63,98.875 312,99.5 326,99.5 58,99.875 62,99.875 64,99.875 313,100.5 315,100.5 317,100.5 319,100.5 77,100.875 79,100.875 314,101.5 316,101.5 318,101.5 326,101.5 64,101.875 74,101.875 76,101.875 78,101.875 275,102.5 313,102.5 315,102.5 317,102.5 319,102.5 75,102.875 77,102.875 79,102.875 314,103.5 316,103.5 318,103.5 326,103.5 64,103.875 72,103.875 74,103.875 76,103.875 78,103.875 203.625,104.5 205.625,104.5 207.625,104.5 209.625,104.5 313,104.5 315,104.5 317,104.5 319,104.5 325,104.5 75,104.875 77,104.875 202.625,105.5 204.625,105.5 206.625,105.5 208.625,105.5 210.625,105.5 314,105.5 318,105.5 320,105.5 322,105.5 324,105.5 326,105.5 64,105.875 72,105.875 74,105.875 76,105.875 78,105.875 203.625,106.5 205.625,106.5 207.625,106.5 209.625,106.5 75,106.875 77,106.875 79,106.875 171.25,107.125 174.5,107.125 178,107.125 181.5,107.125 185,107.125 188.5,107.125 202.625,107.5 204.625,107.5 206.625,107.5 208.625,107.5 210.625,107.5 64,107.875 72,107.875 74,107.875 76,107.875 78,107.875 268.75,108 178,108.5 185,108.5 203.625,108.5 205.625,108.5 207.625,108.5 209.625,108.5 65,108.875 67,108.875 77,108.875 79,108.875 171.25,109 192,109 202.625,109.5 204.625,109.5 206.625,109.5 208.625,109.5 210.625,109.5 184.5,109.75 64,109.875 66,109.875 78,109.875 176,110 177.5,110 190,110 179,110.5 191.5,110.5 203.625,110.5 205.625,110.5 207.625,110.5 209.625,110.5 183.5,110.625 185.375,110.625 171.25,110.75 65,110.875 70.75,110.875 107.25,111 109,111 111,111 113,111 114.75,111 116.75,111 118.75,111 120.5,111 122.5,111 124.5,111 126.25,111 128.25,111 130.25,111 132,111 136,111 137.75,111 139.75,111 141.75,111 143.5,111 145.5,111 147.5,111 149.25,111 151.25,111 176.5,111.5 178,111.5 182.5,111.5 184.5,111.5 186.25,111.5 190.5,111.5 192.5,111.5 202.625,111.5 204.625,111.5 206.625,111.5 208.625,111.5 210.625,111.5 64,111.875 66,111.875 108.125,112 110,112 112,112 113.875,112 119.625,112 121.5,112 123.5,112 125.375,112 131.125,112 133,112 135,112 136.875,112 142.625,112 144.5,112 146.5,112 148.375,112 171.25,112.5 175.5,112.5 179,112.5 183.5,112.5 191.5,112.5 203.625,112.5 205.625,112.5 207.625,112.5 209.625,112.5 70.75,112.875 107.25,113 109,113 111,113 113,113 114.75,113 118.75,113 120.5,113 122.5,113 124.5,113 126.25,113 130.25,113 132,113 136,113 137.75,113 141.75,113 143.5,113 145.5,113 147.5,113 149.25,113 202.625,113.5 204.625,113.5 206.625,113.5 208.625,113.5 210.625,113.5 108.125,114 110,114 112,114 113.875,114 119.625,114 121.5,114 123.5,114 125.375,114 131.125,114 133,114 135,114 136.875,114 142.625,114 144.5,114 146.5,114 148.375,114 175.5,114 179,114 183.5,114 186.5,114 191.5,114 245,114 247,114 249,114 251,114 256,114 258,114 260,114 262,114 171.25,114.25 194.5,114.25 203.625,114.5 205.625,114.5 207.625,114.5 209.625,114.5 70.75,114.875 107.25,115 109,115 111,115 113,115 114.75,115 118.75,115 120.5,115 122.5,115 124.5,115 126.25,115 130.25,115 132,115 136,115 137.75,115 141.75,115 143.5,115 145.5,115 147.5,115 149.25,115 246,115 250,115 252,115 257,115 259,115 202.625,115.5 204.625,115.5 206.625,115.5 208.625,115.5 210.625,115.5 78,115.875 108.125,116 110,116 112,116 113.875,116 119.625,116 121.5,116 123.5,116 125.375,116 131.125,116 133,116 135,116 136.875,116 142.625,116 144.5,116 146.5,116 148.375,116 171.25,116 245,116 251,116 256,116 258,116 203.625,116.5 205.625,116.5 207.625,116.5 209.625,116.5 211.625,116.5 239.375,116.75 241.25,116.75 107.25,117 109,117 111,117 113,117 114.75,117 118.75,117 120.5,117 122.5,117 124.5,117 126.25,117 130.25,117 132,117 136,117 137.75,117 141.75,117 143.5,117 145.5,117 147.5,117 149.25,117 252,117 255,117 257,117 259,117 202.625,117.5 204.625,117.5 206.625,117.5 208.625,117.5 210.625,117.5 214.625,117.5 216.625,117.625 218.625,117.625 220.625,117.625 222.625,117.625 238.25,117.75 240.25,117.75 242.25,117.75 104.25,118 106.25,118 108.125,118 110,118 112,118 113.875,118 115.75,118 117.75,118 119.625,118 121.5,118 123.5,118 125.375,118 127.25,118 129.25,118 131.125,118 133,118 135,118 136.875,118 138.75,118 140.75,118 142.625,118 144.5,118 146.5,118 148.375,118 150.25,118 152.25,118 256,118 203.625,118.5 205.625,118.5 207.625,118.5 209.625,118.5 211.625,118.5 215.625,118.5 217.625,118.5 219.625,118.5 221.625,118.5 239.375,118.75 241.25,118.75 243.25,118.75 250.875,118.75 252.75,118.75 105.25,119 107.25,119 109,119 111,119 113,119 114.75,119 116.75,119 118.75,119 120.5,119 122.5,119 124.5,119 126.25,119 128.25,119 130.25,119 132,119 136,119 137.75,119 139.75,119 141.75,119 143.5,119 145.5,119 147.5,119 149.25,119 151.25,119 255,119 257,119 202.625,119.5 204.625,119.5 206.625,119.5 208.625,119.5 210.625,119.5 214.625,119.5 216.625,119.5 218.625,119.5 220.625,119.5 222.625,119.5 236.5,119.75 238.5,119.75 240.25,119.75 242.25,119.75 244.125,119.75 246,119.75 248,119.75 250,119.75 251.75,119.75 253.75,119.75 102.375,120 104.25,120 106.25,120 108.125,120 113.875,120 115.75,120 117.75,120 119.625,120 125.375,120 127.25,120 129.25,120 131.125,120 136.875,120 138.75,120 140.75,120 142.625,120 148.375,120 150.25,120 152.25,120 154.125,120 203.625,120.5 205.625,120.5 207.625,120.5 209.625,120.5 211.625,120.5 215.625,120.5 217.625,120.5 219.625,120.5 221.625,120.5 239.375,120.75 241.25,120.75 243.25,120.75 245,120.75 250.875,120.75 252.75,120.75 254.75,120.75 256.5,120.75 101.5,121 103.25,121 105.25,121 107.25,121 109,121 113,121 114.75,121 116.75,121 118.75,121 120.5,121 124.5,121 126.25,121 128.25,121 130.25,121 132,121 136,121 137.75,121 139.75,121 141.75,121 143.5,121 147.5,121 149.25,121 151.25,121 153.25,121 202.625,121.5 204.625,121.5 206.625,121.5 208.625,121.5 210.625,121.5 214.625,121.5 216.625,121.5 218.625,121.5 220.625,121.5 222.625,121.5 236.5,121.75 238.5,121.75 240.25,121.75 242.25,121.75 244.125,121.75 246,121.75 248,121.75 250,121.75 251.75,121.75 253.75,121.75 255.75,121.75 257.5,121.75 102.375,122 104.25,122 106.25,122 108.125,122 113.875,122 115.75,122 117.75,122 119.625,122 125.375,122 127.25,122 129.25,122 131.125,122 136.875,122 138.75,122 140.75,122 142.625,122 148.375,122 150.25,122 152.25,122 154.125,122 203.625,122.5 205.625,122.5 207.625,122.5 209.625,122.5 211.625,122.5 215.625,122.5 217.625,122.5 219.625,122.5 221.625,122.5 239.375,122.75 241.25,122.75 243.25,122.75 245,122.75 250.875,122.75 252.75,122.75 254.75,122.75 256.5,122.75 101.5,123 103.25,123 105.25,123 107.25,123 109,123 113,123 114.75,123 116.75,123 118.75,123 120.5,123 124.5,123 126.25,123 128.25,123 130.25,123 132,123 136,123 137.75,123 139.75,123 141.75,123 143.5,123 147.5,123 149.25,123 151.25,123 153.25,123 214.625,123.5 216.625,123.5 218.625,123.5 220.625,123.5 222.625,123.5 236.5,123.75 238.5,123.75 240.25,123.75 242.25,123.75 244.125,123.75 246,123.75 248,123.75 250,123.75 251.75,123.75 253.75,123.75 102.375,124 104.25,124 106.25,124 108.125,124 113.875,124 115.75,124 117.75,124 119.625,124 125.375,124 127.25,124 129.25,124 131.125,124 136.875,124 138.75,124 140.75,124 142.625,124 148.375,124 150.25,124 152.25,124 154.125,124 255,124.5 257,124.5 239.375,124.75 241.25,124.75 243.25,124.75 250.875,124.75 252.75,124.75 99.5,125 101.5,125 103.25,125 105.25,125 107.25,125 109,125 111,125 113,125 114.75,125 116.75,125 118.75,125 120.5,125 122.5,125 124.5,125 126.25,125 128.25,125 130.25,125 132,125 136,125 137.75,125 139.75,125 141.75,125 143.5,125 145.5,125 147.5,125 149.25,125 151.25,125 153.25,125 256,125.5 238.5,125.75 240.25,125.75 242.25,125.75 253.75,125.75 244,126.5 252,126.5 255,126.5 257,126.5 259,126.5 239.375,126.75 241.25,126.75 245,127.5 251,127.5 256,127.5 258,127.5 253.75,127.75 244,128.5 246,128.5 250,128.5 252,128.5 257,128.5 259,128.5 245,129.5 247,129.5 249,129.5 251,129.5 256,129.5 258,129.5 260,129.5 262,129.5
